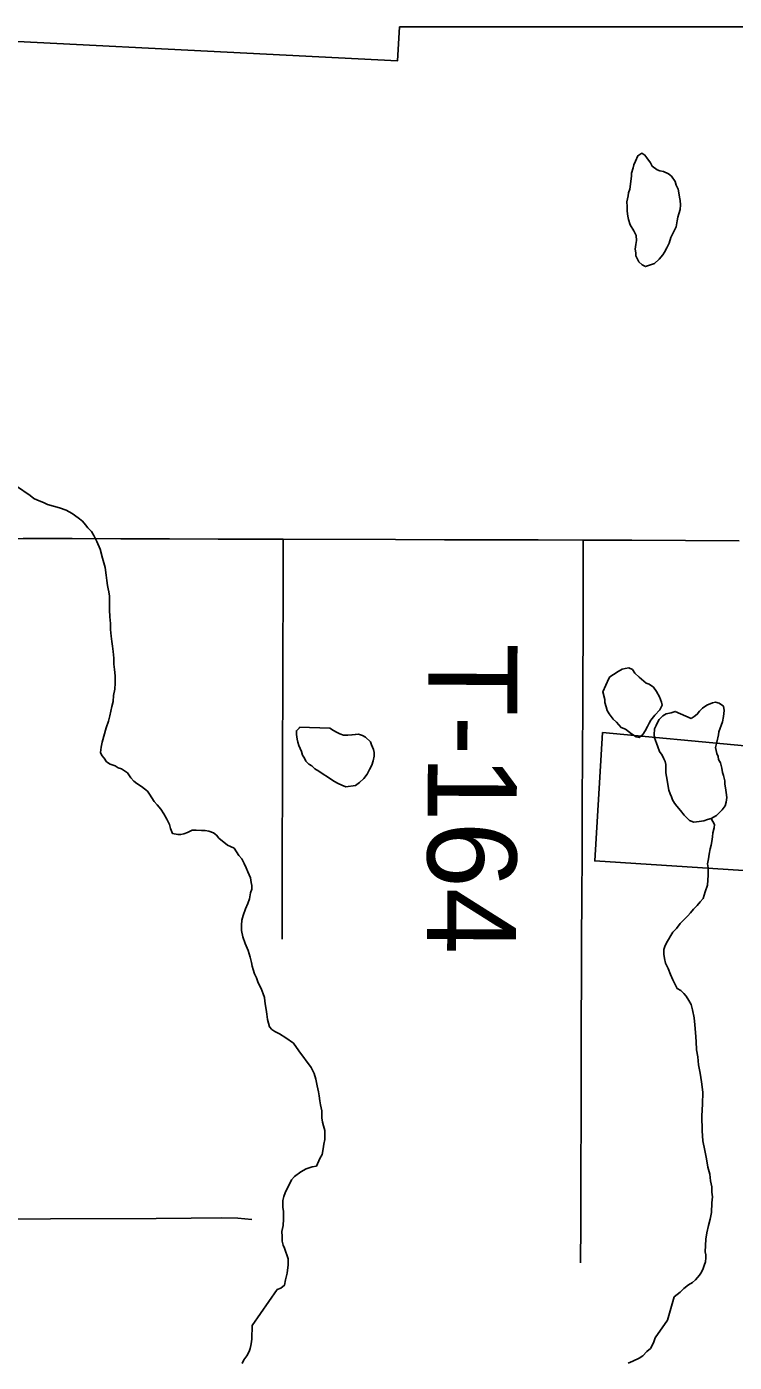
# Model space of a CAD drawing. Extents: x -11.4 to 84.1, y 11.1 to 59.
# Drawn here: x 28.933 to 29.384, y 46.596 to 47.448 of the extents above; entities that cross this region are included whole.
import ezdxf

# ---------------------------------------------------------------- set-up
doc = ezdxf.new("R2010")
doc.units = 0
for name, color, linetype in [('GM_X_Corporation', 7, 'Continuous'), ('GM_X_Minor_Lake', 7, 'Continuous'), ('GM_X_Minor_River', 7, 'Continuous'), ('GM_X_Township_Road', 7, 'Continuous'), ('GM_X_Township_Road_Text', 7, 'Continuous')]:
    doc.layers.add(name, color=color, linetype=linetype)

msp = doc.modelspace()

# ---------------------------------------------------------------- linework, layer by layer
at = {"layer": 'GM_X_Corporation'}
msp.add_line((29.57058, 47.44833), (29.17063, 47.44833), dxfattribs=at)
for points in [[(29.17063, 47.44833), (29.16933, 47.42653), (28.81804, 47.4445), (28.81824, 47.44833)], [(29.4228, 46.90804), (29.29517, 46.9163), (29.30011, 46.99808), (29.39089, 46.98957)]]:
    msp.add_lwpolyline(points, dxfattribs=at)
at = {"layer": 'GM_X_Minor_Lake'}
for points in [[(29.31856, 47.35308), (29.31854, 47.35498), (29.31964, 47.35842), (29.31999, 47.36032), (29.32111, 47.36261), (29.32259, 47.36605), (29.32523, 47.3676), (29.32714, 47.36648), (29.32831, 47.36459), (29.33062, 47.36157), (29.33179, 47.3593), (29.33486, 47.35705), (29.33677, 47.35631), (29.33905, 47.35595), (29.34211, 47.35446), (29.34403, 47.35296), (29.34635, 47.34956), (29.34713, 47.34729), (29.3483, 47.34463), (29.34871, 47.34236), (29.34912, 47.3397), (29.34953, 47.33742), (29.34994, 47.33477), (29.3496, 47.33172), (29.34887, 47.32905), (29.34813, 47.32676), (29.34778, 47.32448), (29.34706, 47.32067), (29.34521, 47.31685), (29.34372, 47.31379), (29.34262, 47.31036), (29.34114, 47.3073), (29.33965, 47.30463), (29.33853, 47.30272), (29.33628, 47.30003), (29.33327, 47.29734), (29.33138, 47.29656), (29.32759, 47.29538), (29.32529, 47.2965), (29.32337, 47.29838), (29.32143, 47.30217), (29.32141, 47.30406), (29.321, 47.30634), (29.32134, 47.30939), (29.32169, 47.31205), (29.32166, 47.31509), (29.3201, 47.31812), (29.31778, 47.3219), (29.3166, 47.32531), (29.31619, 47.32759), (29.31578, 47.33062), (29.31574, 47.33367), (29.31571, 47.3367), (29.31606, 47.33861), (29.31642, 47.34051), (29.31678, 47.34242), (29.31751, 47.34471), (29.31856, 47.35308)], [(29.34521, 47.31685), (29.34706, 47.32067), (29.34778, 47.32448), (29.34813, 47.32676), (29.34887, 47.32905), (29.3496, 47.33172), (29.34994, 47.33477), (29.34953, 47.33742), (29.34912, 47.3397), (29.34871, 47.34236), (29.3483, 47.34463), (29.34713, 47.34729), (29.34635, 47.34956), (29.34403, 47.35296), (29.34211, 47.35446), (29.33905, 47.35595), (29.33677, 47.35631), (29.33486, 47.35705), (29.33179, 47.3593), (29.33062, 47.36157), (29.32831, 47.36459), (29.32714, 47.36648), (29.32523, 47.3676), (29.32259, 47.36605), (29.32111, 47.36261), (29.31999, 47.36032), (29.31964, 47.35842), (29.31854, 47.35498), (29.31856, 47.35308)], [(29.31856, 47.35308), (29.31751, 47.34471), (29.31678, 47.34242), (29.31642, 47.34051), (29.31606, 47.33861), (29.31571, 47.3367), (29.31574, 47.33367), (29.31578, 47.33062), (29.31619, 47.32759), (29.3166, 47.32531), (29.31778, 47.3219), (29.3201, 47.31812), (29.32166, 47.31509), (29.32169, 47.31205), (29.32134, 47.30939), (29.321, 47.30634), (29.32141, 47.30406), (29.32143, 47.30217), (29.32337, 47.29838), (29.32529, 47.2965), (29.32759, 47.29538), (29.33138, 47.29656), (29.33327, 47.29734), (29.33628, 47.30003), (29.33853, 47.30272), (29.33965, 47.30463), (29.34114, 47.3073), (29.34262, 47.31036), (29.34372, 47.31379), (29.34521, 47.31685)], [(29.30405, 47.03264), (29.30478, 47.03358), (29.30704, 47.03512), (29.31006, 47.03705), (29.31271, 47.0386), (29.3146, 47.039), (29.31688, 47.0394), (29.31917, 47.03828), (29.32072, 47.03602), (29.32341, 47.03338), (29.32802, 47.02963), (29.32993, 47.02889), (29.33261, 47.02701), (29.33454, 47.02437), (29.33648, 47.02097), (29.33766, 47.01756), (29.33806, 47.01566), (29.33658, 47.0126), (29.33358, 47.00915), (29.33095, 47.00608), (29.32983, 47.00417), (29.32872, 47.00188), (29.32723, 46.9992), (29.32574, 46.99691), (29.32347, 46.99498), (29.32157, 46.99534), (29.31851, 46.99721), (29.31659, 46.99872), (29.31467, 47.00022), (29.312, 47.00133), (29.30892, 47.00472), (29.307, 47.0066), (29.30429, 47.01), (29.30313, 47.01227), (29.30234, 47.01454), (29.30155, 47.0172), (29.30153, 47.0191), (29.30033, 47.02403), (29.30405, 47.03264)], [(29.30405, 47.03264), (29.30033, 47.02403), (29.30153, 47.0191), (29.30155, 47.0172), (29.30234, 47.01454), (29.30313, 47.01227), (29.30429, 47.01), (29.307, 47.0066), (29.30892, 47.00472), (29.312, 47.00133), (29.31467, 47.00022), (29.31659, 46.99872), (29.31851, 46.99721), (29.32157, 46.99534), (29.32347, 46.99498), (29.32574, 46.99691), (29.32723, 46.9992), (29.32872, 47.00188), (29.32983, 47.00417), (29.33095, 47.00608)], [(29.33095, 47.00608), (29.33358, 47.00915), (29.33658, 47.0126), (29.33806, 47.01566), (29.33766, 47.01756), (29.33648, 47.02097), (29.33454, 47.02437), (29.33261, 47.02701), (29.32993, 47.02889), (29.32802, 47.02963), (29.32341, 47.03338), (29.32072, 47.03602), (29.31917, 47.03828), (29.31688, 47.0394), (29.3146, 47.039), (29.31271, 47.0386), (29.31006, 47.03705), (29.30704, 47.03512), (29.30478, 47.03358), (29.30405, 47.03264)], [(29.35659, 47.00704), (29.35867, 47.00826), (29.36055, 47.0098), (29.36205, 47.01172), (29.36393, 47.01364), (29.36657, 47.01556), (29.37035, 47.01712), (29.37225, 47.01752), (29.37454, 47.01678), (29.37722, 47.01491), (29.37763, 47.01225), (29.3773, 47.00845), (29.37658, 47.00502), (29.37437, 46.99853), (29.37401, 46.99663), (29.37293, 46.99206), (29.37221, 46.98863), (29.37301, 46.98483), (29.37379, 46.98294), (29.37419, 46.98104), (29.37536, 46.97877), (29.37616, 46.97536), (29.37657, 46.9727), (29.37736, 46.97081), (29.37815, 46.96739), (29.37818, 46.96511), (29.37859, 46.96284), (29.379, 46.9598), (29.37942, 46.95676), (29.37907, 46.95372), (29.37834, 46.95143), (29.37647, 46.94875), (29.37459, 46.94683), (29.37271, 46.94529), (29.36931, 46.94335), (29.36704, 46.94257), (29.36477, 46.94179), (29.36173, 46.94138), (29.35831, 46.94096), (29.35564, 46.94208), (29.35218, 46.94546), (29.34986, 46.94848), (29.34755, 46.95112), (29.34601, 46.95301), (29.34484, 46.95527), (29.34406, 46.95717), (29.34328, 46.95906), (29.34249, 46.96134), (29.34087, 46.97006), (29.34047, 46.97234), (29.34043, 46.97538), (29.3404, 46.97766), (29.34, 46.97956), (29.33922, 46.98145), (29.33805, 46.98372), (29.3365, 46.98599), (29.33533, 46.98902), (29.33454, 46.99129), (29.33336, 46.9947), (29.33296, 46.9966), (29.3333, 47.0004), (29.33441, 47.0027), (29.33515, 47.0046), (29.33627, 47.00652), (29.33852, 47.00882), (29.34079, 47.00998), (29.34382, 47.01077), (29.34647, 47.01156), (29.35659, 47.00704)], [(29.36931, 46.94335), (29.37271, 46.94529), (29.37459, 46.94683), (29.37647, 46.94875), (29.37834, 46.95143), (29.37907, 46.95372), (29.37942, 46.95676), (29.379, 46.9598), (29.37859, 46.96284), (29.37818, 46.96511), (29.37815, 46.96739), (29.37736, 46.97081), (29.37657, 46.9727), (29.37616, 46.97536), (29.37536, 46.97877), (29.37419, 46.98104), (29.37379, 46.98294), (29.37301, 46.98483), (29.37221, 46.98863), (29.37293, 46.99206), (29.37401, 46.99663), (29.37437, 46.99853), (29.37658, 47.00502), (29.3773, 47.00845), (29.37763, 47.01225), (29.37722, 47.01491), (29.37454, 47.01678), (29.37225, 47.01752), (29.37035, 47.01712), (29.36657, 47.01556), (29.36393, 47.01364), (29.36205, 47.01172), (29.36055, 47.0098), (29.35867, 47.00826), (29.35659, 47.00704)], [(29.35659, 47.00704), (29.34647, 47.01156), (29.34382, 47.01077), (29.34079, 47.00998), (29.33852, 47.00882), (29.33627, 47.00652), (29.33515, 47.0046), (29.33441, 47.0027), (29.3333, 47.0004), (29.33296, 46.9966), (29.33336, 46.9947), (29.33454, 46.99129), (29.33533, 46.98902), (29.3365, 46.98599), (29.33805, 46.98372), (29.33922, 46.98145), (29.34, 46.97956), (29.3404, 46.97766), (29.34043, 46.97538), (29.34047, 46.97234), (29.34087, 46.97006), (29.34249, 46.96134), (29.34328, 46.95906), (29.34406, 46.95717), (29.34484, 46.95527), (29.34601, 46.95301), (29.34755, 46.95112), (29.34986, 46.94848), (29.35218, 46.94546), (29.35564, 46.94208), (29.35831, 46.94096), (29.36173, 46.94138), (29.36477, 46.94179), (29.36704, 46.94257), (29.36931, 46.94335)], [(29.10673, 47.00156), (29.10673, 47.00118), (29.10673, 47.00118), (29.10485, 46.99926), (29.10488, 46.99698), (29.10529, 46.99394), (29.10569, 46.99205), (29.10648, 46.98977), (29.10726, 46.98788), (29.10805, 46.98599), (29.10883, 46.98371), (29.11, 46.98182), (29.11078, 46.97993), (29.1127, 46.97805), (29.11461, 46.97693), (29.11654, 46.97505), (29.11922, 46.97355), (29.1219, 46.97168), (29.12458, 46.9698), (29.12879, 46.96718), (29.13147, 46.96569), (29.13376, 46.96457), (29.13644, 46.96346), (29.14251, 46.96428)], [(29.10673, 47.00156), (29.12612, 47.001), (29.12842, 46.9995), (29.13033, 46.99838), (29.13262, 46.99726), (29.13491, 46.99652), (29.13758, 46.99655), (29.14024, 46.99657), (29.14251, 46.99698), (29.14441, 46.997), (29.14708, 46.99626), (29.149, 46.99514), (29.15207, 46.99213), (29.15285, 46.99024), (29.15403, 46.98721), (29.15443, 46.98531), (29.15446, 46.98303), (29.15373, 46.97998), (29.153, 46.97731), (29.15151, 46.97464), (29.15003, 46.97158), (29.14778, 46.9689), (29.14515, 46.96621), (29.14251, 46.96428), (29.13644, 46.96346), (29.13376, 46.96457), (29.13147, 46.96569), (29.12879, 46.96718), (29.12458, 46.9698), (29.1219, 46.97168), (29.11922, 46.97355), (29.11654, 46.97505), (29.11461, 46.97693), (29.1127, 46.97805), (29.11078, 46.97993), (29.11, 46.98182), (29.10883, 46.98371), (29.10805, 46.98599), (29.10726, 46.98788), (29.10648, 46.98977), (29.10569, 46.99205), (29.10529, 46.99394), (29.10488, 46.99698), (29.10485, 46.99926), (29.10673, 47.00118), (29.10673, 47.00118), (29.10673, 47.00156)], [(29.14251, 46.96428), (29.14515, 46.96621), (29.14778, 46.9689), (29.15003, 46.97158), (29.15151, 46.97464), (29.153, 46.97731), (29.15373, 46.97998), (29.15446, 46.98303), (29.15443, 46.98531), (29.15403, 46.98721), (29.15285, 46.99024), (29.15207, 46.99213), (29.149, 46.99514), (29.14708, 46.99626), (29.14441, 46.997), (29.14251, 46.99698), (29.14024, 46.99657), (29.13758, 46.99655), (29.13491, 46.99652), (29.13262, 46.99726), (29.13033, 46.99838), (29.12842, 46.9995), (29.12612, 47.001), (29.10673, 47.00156)]]:
    msp.add_lwpolyline(points, dxfattribs=at)
at = {"layer": 'GM_X_Minor_River'}
for points in [[(29.06505, 46.92434), (29.06275, 46.92546), (29.06084, 46.9262), (29.05547, 46.93071), (29.05393, 46.9326), (29.05201, 46.9341), (29.04896, 46.93521), (29.04667, 46.93557), (29.04439, 46.93555), (29.04097, 46.93589), (29.0383, 46.93586), (29.03528, 46.93431), (29.03301, 46.93353), (29.03111, 46.93313), (29.02921, 46.93311), (29.02578, 46.93384), (29.02461, 46.93687), (29.02382, 46.93952), (29.02226, 46.94293), (29.02032, 46.94633), (29.01838, 46.94935), (29.01607, 46.95199), (29.01414, 46.95425), (29.01259, 46.95652), (29.01105, 46.95879), (29.00989, 46.96067), (29.00797, 46.96217), (29.00605, 46.96368), (29.00299, 46.96555), (29.00107, 46.96705), (28.99914, 46.96931), (28.99721, 46.97233), (28.99337, 46.97496), (28.99108, 46.97569), (28.98917, 46.97682), (28.98612, 46.97793), (28.98382, 46.97942), (28.98227, 46.98169), (28.98073, 46.98357), (28.97995, 46.98547), (28.98029, 46.98889), (28.98101, 46.99194), (28.98357, 47.00109), (28.98504, 47.00529), (28.98576, 47.00872), (28.98648, 47.01177), (28.98721, 47.01481), (28.98793, 47.01786), (28.98827, 47.02167), (28.98898, 47.02586), (28.98932, 47.02967), (28.98929, 47.03233), (28.98926, 47.03423), (28.98883, 47.0384), (28.98842, 47.04182), (28.98837, 47.04562), (28.98794, 47.0498), (28.98752, 47.05322), (28.98711, 47.05626), (28.98669, 47.05967), (28.98626, 47.06385), (28.98622, 47.06765), (28.98579, 47.07183), (28.98573, 47.07639), (28.98568, 47.08058), (28.98563, 47.08514), (28.98522, 47.08779), (28.98482, 47.08969), (28.98441, 47.09197), (28.984, 47.09501), (28.98358, 47.09842), (28.98276, 47.10336), (28.98117, 47.10943), (28.97958, 47.11511), (28.97762, 47.12003), (28.97568, 47.12382), (28.97413, 47.12646), (28.97182, 47.12872), (28.97028, 47.13061), (28.96835, 47.13287), (28.96566, 47.13512), (28.96183, 47.13775), (28.958, 47.13999), (28.95381, 47.14147), (28.94999, 47.14257), (28.94618, 47.14367), (28.9435, 47.14479), (28.93968, 47.14627), (28.93739, 47.14739), (28.93509, 47.14927), (28.92628, 47.15526)], [(29.34149, 46.62335), (29.34586, 46.6382), (29.34963, 46.64128), (29.35188, 46.64358), (29.3549, 46.64589), (29.35754, 46.64744), (29.35942, 46.64898), (29.36205, 46.65205), (29.36317, 46.65396), (29.36428, 46.65625), (29.36502, 46.65816), (29.36575, 46.66045), (29.3661, 46.66311), (29.36608, 46.66502), (29.36568, 46.66691), (29.36597, 46.6749), (29.36668, 46.67909), (29.36776, 46.68366), (29.36886, 46.68785), (29.36957, 46.69204), (29.36988, 46.69813), (29.37021, 46.70194), (29.3698, 46.70497), (29.36976, 46.7084), (29.36895, 46.71219), (29.36852, 46.71637), (29.36733, 46.72092), (29.36651, 46.72623), (29.36531, 46.73154), (29.3641, 46.73761), (29.36364, 46.74407), (29.36353, 46.75358), (29.36382, 46.76118), (29.36411, 46.76879), (29.36328, 46.77525), (29.36245, 46.78094), (29.36125, 46.78625), (29.36081, 46.79119), (29.36, 46.79574), (29.35994, 46.80106), (29.35949, 46.80676), (29.35906, 46.8117), (29.35862, 46.81626), (29.35743, 46.82119), (29.35662, 46.8246), (29.35507, 46.82725), (29.35352, 46.8299), (29.35198, 46.83178), (29.35006, 46.83366), (29.34776, 46.83478), (29.34621, 46.83781), (29.34504, 46.84046), (29.34348, 46.84386), (29.34191, 46.84765), (29.34035, 46.85106), (29.33956, 46.85409), (29.33915, 46.85675), (29.33911, 46.85979), (29.33985, 46.8617), (29.34096, 46.86399), (29.34506, 46.87087), (29.34732, 46.87318), (29.34956, 46.87624), (29.35182, 46.87855), (29.35445, 46.88123), (29.35633, 46.88315), (29.3582, 46.88545), (29.36045, 46.88776), (29.36233, 46.89006), (29.3642, 46.89236), (29.36567, 46.89655), (29.36715, 46.90075), (29.36745, 46.90722), (29.3674, 46.91178), (29.36698, 46.91444), (29.36771, 46.91749), (29.36805, 46.92053), (29.36877, 46.92396), (29.36951, 46.92625), (29.36986, 46.92853), (29.37021, 46.93158), (29.37056, 46.93424), (29.37128, 46.93729), (29.37163, 46.93958), (29.36931, 46.94335)], [(29.07662, 46.61986), (29.09264, 46.64289), (29.09492, 46.64368), (29.09718, 46.6456), (29.0979, 46.64903), (29.09899, 46.65322), (29.09968, 46.65855), (29.09964, 46.66235), (29.09728, 46.66917), (29.0965, 46.67107), (29.09571, 46.67372), (29.09567, 46.67676), (29.09564, 46.6798), (29.09635, 46.68361), (29.09668, 46.6878), (29.09666, 46.69008), (29.09663, 46.69274), (29.09622, 46.6954), (29.09619, 46.6973), (29.09617, 46.69958), (29.0969, 46.70225), (29.09763, 46.70453), (29.09875, 46.70683), (29.09986, 46.70874), (29.10171, 46.71294), (29.10359, 46.71486), (29.10774, 46.71794), (29.11114, 46.71988), (29.11493, 46.72106), (29.11758, 46.72146), (29.1198, 46.72643), (29.12129, 46.7291), (29.12201, 46.73253), (29.12236, 46.73558), (29.12308, 46.73863), (29.12305, 46.74129), (29.12302, 46.74433), (29.12222, 46.74736), (29.12143, 46.74964), (29.12102, 46.75229), (29.121, 46.75457), (29.12097, 46.75686), (29.12017, 46.76065), (29.11976, 46.76331), (29.11934, 46.76634), (29.11893, 46.769), (29.11813, 46.7728), (29.11732, 46.77697), (29.11613, 46.78076), (29.11419, 46.78454), (29.10646, 46.79511), (29.10298, 46.80002), (29.098, 46.80339), (29.09417, 46.80601), (29.09111, 46.80751), (29.0892, 46.80863), (29.08766, 46.81051), (29.08646, 46.81506), (29.08604, 46.81848), (29.08563, 46.82152), (29.08522, 46.8238), (29.08481, 46.82683), (29.0844, 46.82911), (29.08361, 46.83138), (29.08243, 46.83479), (29.08049, 46.83858), (29.07931, 46.8416), (29.07814, 46.84425), (29.07735, 46.84691), (29.07656, 46.84918), (29.07616, 46.85146), (29.07536, 46.85487), (29.07417, 46.85904), (29.07222, 46.86359), (29.07065, 46.86775), (29.06984, 46.87193), (29.0698, 46.87535), (29.07014, 46.87839), (29.07087, 46.88144), (29.07234, 46.88564), (29.07382, 46.88907), (29.07493, 46.89213), (29.07564, 46.89594), (29.07637, 46.89822), (29.07635, 46.90051), (29.07595, 46.9024), (29.07553, 46.90544), (29.07475, 46.90733), (29.07397, 46.90923), (29.07279, 46.91188), (29.07162, 46.91452), (29.07007, 46.91755), (29.06814, 46.91981), (29.06659, 46.92208), (29.06505, 46.92434)], [(29.3164, 46.59591), (29.31941, 46.5971), (29.32356, 46.59907), (29.32581, 46.60062), (29.32842, 46.60333), (29.33067, 46.60527), (29.33178, 46.60719), (29.33288, 46.60949), (29.33359, 46.61216), (29.34149, 46.62335)], [(29.07028, 46.59566), (29.07138, 46.59796), (29.07323, 46.60065), (29.07471, 46.60334), (29.07543, 46.60525), (29.07578, 46.60716), (29.07613, 46.60945), (29.07647, 46.61135), (29.07662, 46.61986)]]:
    msp.add_lwpolyline(points, dxfattribs=at)
at = {"layer": 'GM_X_Township_Road'}
for points in [[(28.47152, 47.12226), (28.76979, 47.12215), (28.79008, 47.12197), (28.81036, 47.12178), (28.93064, 47.12187), (28.96171, 47.12179), (28.99278, 47.1217), (29.02385, 47.12161), (29.05492, 47.12152), (29.09644, 47.12141), (29.16815, 47.12121), (29.19922, 47.12112), (29.23029, 47.12103), (29.25905, 47.12095), (29.2878, 47.12087), (29.31887, 47.12078), (29.38733, 47.12046)], [(29.09568, 46.86628), (29.09577, 46.89735), (29.09586, 46.92842), (29.09596, 46.95949), (29.09605, 46.99056), (29.09614, 47.02163), (29.09624, 47.0527), (29.09632, 47.08376), (29.09644, 47.12141)], [(29.28615, 46.65996), (29.28635, 46.68386), (29.28647, 46.78761), (29.28655, 46.81199), (29.28667, 46.84306), (29.28677, 46.86699), (29.28687, 46.89092), (29.28703, 46.92199), (29.2872, 46.95306), (29.28737, 46.98413), (29.28754, 47.0152), (29.28765, 47.03633), (29.28776, 47.05748), (29.2878, 47.12087)], [(28.917, 46.68784), (28.94806, 46.68791), (29.01534, 46.68815), (29.03777, 46.68829), (29.05715, 46.68852), (29.0675, 46.68836), (29.07638, 46.68755)]]:
    msp.add_lwpolyline(points, dxfattribs=at)

# ---------------------------------------------------------------- texts
at = {"layer": 'GM_X_Township_Road_Text'}
msp.add_text('T-164', height=0.056818, rotation=269.71896, dxfattribs=at).set_placement((29.18909, 47.05539))

doc.saveas('drawing.dxf')
